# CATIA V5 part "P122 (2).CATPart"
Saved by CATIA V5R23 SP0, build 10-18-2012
Part number: 05-LICP-T02-E-S11-P122 (2)
Definition: butee a aiguilles
Description: butee_a_aiguilles_ax_5_40_60_02
Bounding box of the stored display mesh (mm): x 2.991 to 4.992, y -27.375 to 27.375, z -27.375 to 27.375
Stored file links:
  C:\wamp\www\COURS\CONCEPTION GMP1\TITRE 02-SEMESTRE 2\03-TP7-PRESSE MECANIQUE\eleve\P122 (2).CATPart
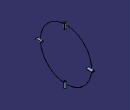
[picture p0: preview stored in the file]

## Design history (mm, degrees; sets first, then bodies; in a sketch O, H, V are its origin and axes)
Body1 (main body)
  Solid1: solid without history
